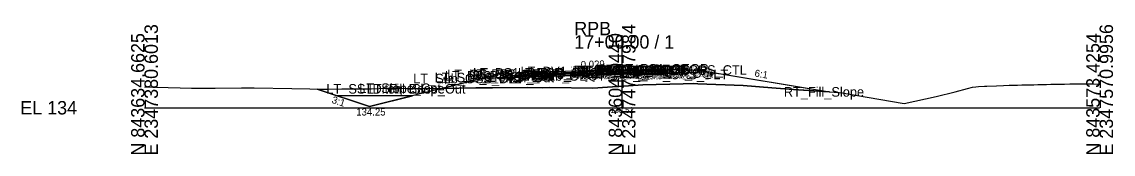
# Model space of a CAD drawing. Extents: x -76 to 2347760, y -10 to 844216.
# Drawn here: x -25.7 to 202.8, y 1990.3 to 2018 of the extents above; entities that cross this region are included whole.
import ezdxf

# ---------------------------------------------------------------- set-up
doc = ezdxf.new("R2010")
doc.units = 0
for name, color, linetype in [('Default', 7, 'Continuous'), ('Exist Cross Section Cell', 7, 'Continuous'), ('Exist XS Center Line Elevation Label', 7, 'Continuous'), ('Exist XS Ground Line', 7, 'Continuous'), ('Prop CMT Pvmt Course 1', 7, 'Continuous'), ('Prop CMT Pvmt Course 2', 7, 'Continuous'), ('Prop CMT Pvmt Course 3', 7, 'Continuous'), ('Prop CMT Pvmt Surface', 7, 'Continuous'), ('Prop CMT Pvmt Surface Shoulder', 7, 'Continuous'), ('Prop CMT Shld Paved Course 1', 7, 'Continuous'), ('Prop CMT Shld Paved Course 2', 7, 'Continuous'), ('Prop CMT Shld Paved Course 3', 7, 'Continuous'), ('Prop CMT Slope Grass', 7, 'Continuous'), ('Prop CMT Subgrade Earthwork', 7, 'Continuous'), ('Prop Road Sect_ Recs - UUC (Outline)', 7, 'Continuous'), ('Prop XS Ditch Standard Text', 7, 'Continuous'), ('Prop XS Earthwork Shape', 7, 'Continuous'), ('Prop XS SE Text', 7, 'Continuous'), ('Prop XS Side Slope Text', 7, 'Continuous'), ('Scratch_Level_0', 7, 'Continuous')]:
    doc.layers.add(name, color=color, linetype=linetype)

msp = doc.modelspace()

# ---------------------------------------------------------------- linework, layer by layer
at = {"layer": 'Exist Cross Section Cell'}
for p, q in [((100, 2000), (100, 2015.16)), ((0, 2000), (100, 2000)), ((100, 2000), (200, 2000))]:
    msp.add_line(p, q, dxfattribs=at)
at = {"layer": 'Exist XS Ground Line'}
msp.add_lwpolyline([(0, 2004.37), (7.44, 2004.16), (9.81, 2004.09), (14.79, 2004.11), (20.31, 2004.14), (22.93, 2004.14), (30.82, 2004.06), (38.41, 2003.86), (41.32, 2003.93), (47.45, 2003.97), (50.76, 2004.08), (51.83, 2004.13), (53.9, 2004.09), (62.33, 2004.01), (69.38, 2004.16), (72.84, 2004.15), (80.12, 2004.22), (83.34, 2004.2), (84.87, 2004.21), (93.85, 2004.12), (100, 2004.52), (100.36, 2004.54), (104.35, 2004.77), (112.78, 2005.02), (114.86, 2005.05), (115.84, 2005.02), (125.36, 2004.62), (131.33, 2004.16), (135.87, 2003.83), (145.44, 2003.18), (146.14, 2003.14), (146.47, 2003.08), (159.05, 2000.87), (165.76, 2002.38), (169.76, 2003.34), (172.36, 2004.06), (173.38, 2004.34), (174.06, 2004.37), (174.61, 2004.41), (175.9, 2004.49), (176.37, 2004.51), (178.38, 2004.59), (179.88, 2004.65), (181.03, 2004.7), (181.87, 2004.72), (182.79, 2004.74), (183.69, 2004.76), (184.46, 2004.78), (185.8, 2004.82), (186.22, 2004.82), (187.05, 2004.84), (188.85, 2004.88), (189.76, 2004.9), (191.46, 2004.94), (192.65, 2004.96), (193.73, 2004.98), (194.24, 2004.98), (195.83, 2005), (196.41, 2004.99), (196.71, 2005), (198.69, 2004.97), (199.59, 2004.96), (200, 2004.95)], dxfattribs=at)
at = {"layer": 'Prop CMT Pvmt Course 1'}
for p, q in [((100, 2007.91), (88, 2007.57)), ((88, 2007.32), (100, 2007.66)), ((88, 2007.57), (88, 2007.32)), ((100, 2007.91), (104, 2008.03)), ((100, 2007.66), (100, 2007.91)), ((100, 2007.66), (100, 2007.91)), ((100, 2007.66), (100, 2007.79)), ((100, 2007.79), (100, 2007.79)), ((100, 2007.79), (100, 2007.66)), ((100, 2007.66), (100, 2007.79)), ((100, 2007.79), (100, 2007.79)), ((100, 2007.79), (100, 2007.66)), ((104, 2007.78), (100, 2007.66)), ((100, 2007.66), (100, 2007.66)), ((100, 2007.66), (100, 2007.66)), ((104, 2008.03), (104, 2007.78))]:
    msp.add_line(p, q, dxfattribs=at)
at = {"layer": 'Prop CMT Pvmt Course 2'}
for p, q in [((100, 2007.66), (88, 2007.32)), ((88, 2006.99), (100, 2007.33)), ((88, 2007.32), (88, 2006.99)), ((100, 2007.66), (104, 2007.78)), ((100, 2007.33), (100, 2007.66)), ((100, 2007.33), (100, 2007.66)), ((104, 2007.44), (100, 2007.33)), ((104, 2007.78), (104, 2007.44))]:
    msp.add_line(p, q, dxfattribs=at)
at = {"layer": 'Prop CMT Pvmt Course 3'}
for p, q in [((100, 2007.33), (88, 2006.99)), ((88, 2006.65), (100, 2007)), ((88, 2006.99), (88, 2006.65)), ((100, 2007.33), (104, 2007.44)), ((100, 2007), (100, 2007.33)), ((100, 2007), (100, 2007.33)), ((104, 2007.11), (100, 2007)), ((104, 2007.44), (104, 2007.11))]:
    msp.add_line(p, q, dxfattribs=at)
at = {"layer": 'Prop CMT Pvmt Surface'}
for q in [(88, 2007.57), (104, 2008.03)]:
    msp.add_line((100, 2007.91), q, dxfattribs=at)
at = {"layer": 'Prop CMT Pvmt Surface Shoulder'}
for p, q in [((88, 2007.57), (78, 2007.28)), ((104, 2008.03), (108, 2008.14))]:
    msp.add_line(p, q, dxfattribs=at)
at = {"layer": 'Prop CMT Shld Paved Course 1'}
for p, q in [((77.74, 2007.03), (88, 2007.32)), ((78, 2007.28), (77.74, 2007.03)), ((88, 2007.57), (78, 2007.28)), ((88, 2007.32), (88, 2007.57)), ((104, 2008.03), (108, 2008.14)), ((104, 2007.78), (104, 2008.03)), ((108.24, 2007.9), (104, 2007.78)), ((108, 2008.14), (108.24, 2007.9))]:
    msp.add_line(p, q, dxfattribs=at)
at = {"layer": 'Prop CMT Shld Paved Course 2'}
for p, q in [((77.74, 2007.03), (77.4, 2006.68)), ((77.4, 2006.68), (88, 2006.99)), ((88, 2007.32), (77.74, 2007.03)), ((88, 2006.99), (88, 2007.32)), ((104, 2007.78), (108.24, 2007.9)), ((104, 2007.44), (104, 2007.78)), ((108.57, 2007.57), (104, 2007.44)), ((108.24, 2007.9), (108.57, 2007.57))]:
    msp.add_line(p, q, dxfattribs=at)
at = {"layer": 'Prop CMT Shld Paved Course 3'}
for p, q in [((76.9, 2006.67), (76.56, 2006.33)), ((76.56, 2006.33), (88, 2006.65)), ((77.4, 2006.68), (76.9, 2006.67)), ((88, 2006.99), (77.4, 2006.68)), ((88, 2006.65), (88, 2006.99)), ((104, 2007.44), (108.57, 2007.57)), ((104, 2007.11), (104, 2007.44)), ((109.39, 2007.26), (104, 2007.11)), ((108.57, 2007.57), (109.07, 2007.59)), ((109.07, 2007.59), (109.39, 2007.26))]:
    msp.add_line(p, q, dxfattribs=at)
at = {"layer": 'Prop CMT Slope Grass'}
for p, q in [((74, 2006.96), (47.14, 2000.25)), ((78, 2007.28), (74, 2006.96)), ((108, 2008.14), (116, 2007.89)), ((116, 2007.89), (143.41, 2003.32)), ((36.14, 2003.92), (47.14, 2000.25))]:
    msp.add_line(p, q, dxfattribs=at)
at = {"layer": 'Prop CMT Subgrade Earthwork'}
for p, q in [((88, 2006.65), (76.56, 2006.33)), ((100, 2007), (88, 2006.65)), ((100, 2007), (104, 2007.11)), ((104, 2007.11), (118.24, 2007.52)), ((76.56, 2006.33), (70.79, 2006.16))]:
    msp.add_line(p, q, dxfattribs=at)
at = {"layer": 'Prop Road Sect_ Recs - UUC (Outline)'}
msp.add_lwpolyline([(40.39, 2002.5), (47.14, 2000.25), (56.14, 2002.5)], close=True, dxfattribs=at)
at = {"layer": 'Prop XS Earthwork Shape'}
for points in [[(100, 2007), (104, 2007.11), (118.24, 2007.52), (143.41, 2003.32), (135.87, 2003.83), (131.33, 2004.16), (125.36, 2004.62), (115.84, 2005.02), (114.86, 2005.05), (112.78, 2005.02), (104.35, 2004.77), (100.36, 2004.54), (100, 2004.52), (93.85, 2004.12), (84.87, 2004.21), (83.34, 2004.2), (80.12, 2004.22), (72.84, 2004.15), (69.38, 2004.16), (62.33, 2004.01), (62.2, 2004.01), (70.79, 2006.16), (76.56, 2006.33), (88, 2006.65)], [(53.9, 2004.09), (62.2, 2004.01), (47.14, 2000.25), (36.14, 2003.92), (38.41, 2003.86), (41.32, 2003.93), (47.45, 2003.97), (50.76, 2004.08), (51.83, 2004.13)]]:
    msp.add_lwpolyline(points, close=True, dxfattribs=at)

# ---------------------------------------------------------------- texts
at = {"layer": 'Default'}
msp.add_text('-', height=0.0001, dxfattribs=at).set_placement((0, 2000))
at = {"layer": 'Exist Cross Section Cell'}
for s, p in [('RPB', (90, 2015.16)), ('17+00.00 / 1', (90, 2012.36)), ('EL 134', (-26, 1998.6))]:
    msp.add_text(s, height=2.8, dxfattribs=at).set_placement(p)
for s, p in [('E 2347380.6013', (2.8, 1990)), ('E 2347475.7984', (102.8, 1990)), ('E 2347570.9956', (202.8, 1990)), ('N 843634.6625', (0, 1990)), ('N 843604.0440', (100, 1990)), ('N 843573.4254', (200, 1990))]:
    msp.add_text(s, height=2.8, rotation=90, dxfattribs=at).set_placement(p)
at = {"layer": 'Exist XS Center Line Elevation Label'}
msp.add_text('138.52', height=1.2, dxfattribs=at).set_placement((97.55, 1998.92))
at = {"layer": 'Prop XS Ditch Standard Text'}
msp.add_text('134.25', height=1.5, dxfattribs=at).set_placement((44.34, 1998.38))
at = {"layer": 'Prop XS SE Text'}
msp.add_text('0.029', height=1.5, rotation=1.6332, dxfattribs=at).set_placement((91.37, 2008.27))
at = {"layer": 'Prop XS Side Slope Text'}
for s, rotation, p in [('4:1', 14.0362, (62.32, 2004.75)), ('6:1', 350.5377, (127.66, 2006.54)), ('3:1', 341.6601, (39.09, 2001.06))]:
    msp.add_text(s, height=1.5, rotation=rotation, dxfattribs=at).set_placement(p)
at = {"layer": 'Scratch_Level_0'}
for s, p in [('RT_PV1_OEEOP', (89.83, 2006.79)), ('LT_PV1_OEEOP', (89.87, 2006.79)), ('RT_PV1_IEEOP', (90.47, 2006.79)), ('LT_PV1_IEEOP', (90.52, 2006.79)), ('RT_PV2_OEOT', (94.13, 2006.78)), ('PV1_PGL', (94.47, 2006.91)), ('RT_PV1_OEOT', (94.69, 2007.03)), ('RT_PS2_OEOP', (98.43, 2006.9)), ('RT_PS1_OEOP', (98.76, 2007.14)), ('RT_GS_OS_CTL', (105.32, 2006.89)), ('LT_Sub_OSS_DLT', (56.26, 2005.11)), ('LT_Sub_Trench_Out', (60.76, 2005.33)), ('LT_PS3_Shelf_Out', (62.88, 2005.67)), ('LT_GS_OS_CTL', (63.37, 2005.96)), ('LT_PS3_OEOP', (67.64, 2005.68)), ('LT_PS2_OEOP', (67.98, 2006.03)), ('LT_PS1_OEOP', (68.8, 2006.28)), ('LT_Sub_OEOT', (78.08, 2005.65)), ('LT_PV2_OEOT', (78.17, 2006.32)), ('LT_PV3_OEOT', (78.17, 2005.99)), ('LT_PV1_OEOT', (78.74, 2006.57)), ('RT_Sub_OEEOP', (89.17, 2006)), ('LT_Sub_OEEOP', (89.21, 2006)), ('RT_PV2_OEEOP', (89.26, 2006.66)), ('RT_PV3_OEEOP', (89.26, 2006.33)), ('LT_PV2_OEEOP', (89.31, 2006.66)), ('LT_PV3_OEEOP', (89.31, 2006.33)), ('RT_PV2_IEEOP', (89.91, 2006.66)), ('LT_PV2_IEEOP', (89.95, 2006.66)), ('RT_Sub_Trench_Out', (93.55, 2006.26)), ('PV2_PGL', (93.91, 2006.66)), ('RT_Sub_OEOT', (94.03, 2006.11)), ('RT_PV3_OEOT', (94.13, 2006.44)), ('RT_PS3_Shelf_Out', (95, 2006.59)), ('RT_Sub_OSS_DLT', (98.75, 2005.97)), ('RT_PS3_OEOP', (98.76, 2006.57)), ('LT_SS_Ditch_Base_Out', (38.08, 2002.96)), ('LT_Slope_Cut', (44.96, 2003.08)), ('LT_Fill_Slope', (46.52, 2002.96)), ('RT_Fill_Slope', (133.88, 2002.32))]:
    msp.add_text(s, height=2, dxfattribs=at).set_placement(p)

doc.saveas('drawing.dxf')
